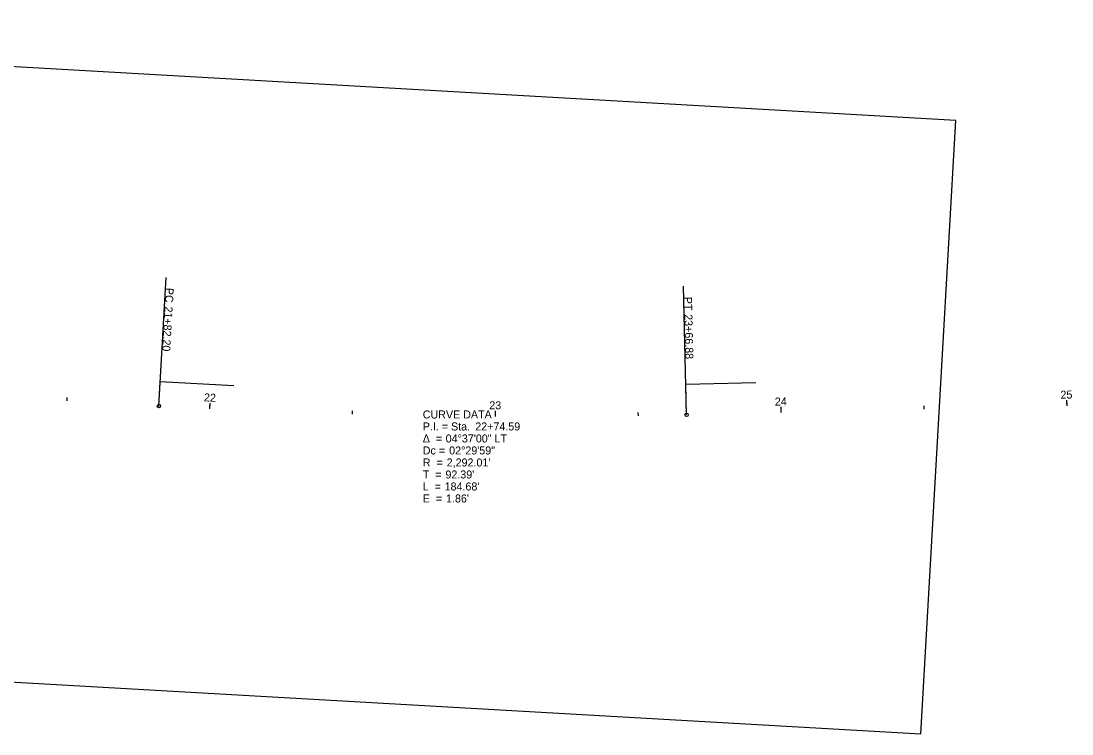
# Model space of a CAD drawing. Extents: x 2273904 to 2275374, y 654586 to 654897.
# Drawn here: x 2274639.3 to 2275006.9, y 654585.8 to 654835.2 of the extents above; entities that cross this region are included whole.
import ezdxf

# ---------------------------------------------------------------- set-up
doc = ezdxf.new("R2010")
doc.units = 0
for name, color, linetype in [('DR_P_Cells', 7, 'Continuous'), ('DR_P_Ditch', 7, 'Continuous'), ('DR_P_Erosion_Control', 7, 'Continuous'), ('GK_Drainage_Nodes', 7, 'Continuous'), ('SC_Scratch1', 7, 'Continuous'), ('SC_Scratch10', 7, 'Continuous'), ('SH_Named_Boundary', 7, 'Continuous')]:
    doc.layers.add(name, color=color, linetype=linetype)

msp = doc.modelspace()

# ---------------------------------------------------------------- linework, layer by layer
at = {"layer": 'DR_P_Ditch'}
for p, q in [((2274687.5, 654700.52), (2274690.07, 654745.45)), ((2274872.11, 654697.43), (2274871.05, 654742.42)), ((2274705.28, 654699.57), (2274705.34, 654700.77)), ((2275005.19, 654700.57), (2275005.15, 654702.57)), ((2274805.23, 654696.83), (2274805.24, 654698.03)), ((2274905.22, 654698.22), (2274905.19, 654699.42))]:
    msp.add_line(p, q, dxfattribs=at)
for centre in [(2274687.5, 654700.52), (2274872.11, 654697.43)]:
    msp.add_circle(centre, 0.6, dxfattribs=at)
at = {"layer": 'DR_P_Erosion_Control'}
for p, q in [((2274687.5, 654700.52), (2274690.07, 654745.45)), ((2274872.11, 654697.43), (2274871.05, 654742.42)), ((2274687.5, 654700.52), (2274687.99, 654709.04)), ((2274713.77, 654707.57), (2274687.99, 654709.04)), ((2274871.86, 654708.18), (2274896.32, 654708.76)), ((2274872.11, 654697.43), (2274871.86, 654708.18)), ((2274655.36, 654702.35), (2274655.43, 654703.55)), ((2274705.28, 654699.57), (2274705.38, 654701.57)), ((2275005.19, 654700.57), (2275005.15, 654702.57)), ((2274755.24, 654697.66), (2274755.28, 654698.86)), ((2274805.23, 654696.83), (2274805.25, 654698.83)), ((2274855.23, 654697.1), (2274855.21, 654698.3)), ((2274905.22, 654698.22), (2274905.17, 654700.21)), ((2274955.21, 654699.39), (2274955.18, 654700.59))]:
    msp.add_line(p, q, dxfattribs=at)
for centre in [(2274687.5, 654700.52), (2274687.5, 654700.52), (2274872.11, 654697.43), (2274872.11, 654697.43)]:
    msp.add_circle(centre, 0.6, dxfattribs=at)
at = {"layer": 'SC_Scratch1'}
for p, q in [((2274687.5, 654700.52), (2274690.07, 654745.45)), ((2274872.11, 654697.43), (2274871.05, 654742.42)), ((2275005.19, 654700.57), (2275005.16, 654701.77))]:
    msp.add_line(p, q, dxfattribs=at)
for centre in [(2274687.5, 654700.52), (2274872.11, 654697.43)]:
    msp.add_circle(centre, 0.6, dxfattribs=at)
at = {"layer": 'SH_Named_Boundary'}
msp.add_lwpolyline([(2274345.01, 654620.55), (2274954.02, 654585.8), (2274966.26, 654800.45), (2274357.26, 654835.2)], close=True, dxfattribs=at)

# ---------------------------------------------------------------- texts
at = {"layer": 'DR_P_Cells'}
for s, p in [('CURVE DATA', (2274779.81, 654696.18)), ('P.I. = Sta. ', (2274779.81, 654691.98)), ('22+74.59', (2274798.18, 654691.98)), ('Δ  = ', (2274779.81, 654687.78)), ('04°37\'00" LT', (2274787.83, 654687.78)), ('Dc = ', (2274779.81, 654683.58)), ('02°29\'59"', (2274789.05, 654683.58)), ('R  = ', (2274779.81, 654679.38)), ("2,292.01'", (2274788.18, 654679.38)), ('T  = ', (2274779.81, 654675.18)), ("92.39'", (2274787.74, 654675.18)), ('L  = ', (2274779.81, 654670.98)), ("184.68'", (2274787.45, 654670.98)), ('E  = ', (2274779.81, 654666.78)), ("1.86'", (2274787.96, 654666.78))]:
    msp.add_text(s, height=2.8, dxfattribs=at).set_placement(p)
at = {"layer": 'DR_P_Ditch'}
for s, rotation, p in [('PC', 266.7343, (2274689.92, 654741.94)), ('PT', 271.351, (2274871.18, 654738.69)), ('21+82.20', 266.7343, (2274689.54, 654735.43)), ('23+66.88', 271.351, (2274871.33, 654732.61)), ('25', 1.351, (2275002.93, 654703.07))]:
    msp.add_text(s, height=2.8, rotation=rotation, dxfattribs=at).set_placement(p)
at = {"layer": 'DR_P_Erosion_Control'}
for s, rotation, p in [('PC', 266.7343, (2274689.92, 654741.94)), ('PT', 271.351, (2274871.18, 654738.69)), ('21+82.20', 266.7343, (2274689.54, 654735.43)), ('23+66.88', 271.351, (2274871.33, 654732.61)), ('22', 357.1793, (2274703.22, 654702.18)), ('25', 1.351, (2275002.93, 654703.07)), ('23', 359.6791, (2274803.07, 654699.39)), ('24', 1.351, (2274903.01, 654700.66))]:
    msp.add_text(s, height=2.8, rotation=rotation, dxfattribs=at).set_placement(p)
at = {"layer": 'GK_Drainage_Nodes'}
for s, p in [('CURVE DATA', (2274779.81, 654696.18)), ('P.I. = Sta. ', (2274779.81, 654691.98)), ('22+74.59', (2274798.18, 654691.98)), ('Δ  = ', (2274779.81, 654687.78)), ('04°37\'00" LT', (2274787.83, 654687.78)), ('Dc = ', (2274779.81, 654683.58)), ('02°29\'59"', (2274789.05, 654683.58)), ('R  = ', (2274779.81, 654679.38)), ("2,292.01'", (2274788.18, 654679.38)), ('T  = ', (2274779.81, 654675.18)), ("92.39'", (2274787.74, 654675.18)), ('L  = ', (2274779.81, 654670.98)), ("184.68'", (2274787.45, 654670.98)), ('E  = ', (2274779.81, 654666.78)), ("1.86'", (2274787.96, 654666.78))]:
    msp.add_text(s, height=2.8, dxfattribs=at).set_placement(p)
at = {"layer": 'SC_Scratch1'}
for s, rotation, p in [('PC', 266.7343, (2274689.92, 654741.94)), ('PT', 271.351, (2274871.18, 654738.69)), ('21+82.20', 266.7343, (2274689.54, 654735.43)), ('23+66.88', 271.351, (2274871.33, 654732.61))]:
    msp.add_text(s, height=2.8, rotation=rotation, dxfattribs=at).set_placement(p)
at = {"layer": 'SC_Scratch10'}
for s, p in [('CURVE DATA', (2274779.81, 654696.18)), ('P.I. = Sta. ', (2274779.81, 654691.98)), ('22+74.59', (2274798.18, 654691.98)), ('Δ  = ', (2274779.81, 654687.78)), ('04°37\'00" LT', (2274787.83, 654687.78)), ('Dc = ', (2274779.81, 654683.58)), ('02°29\'59"', (2274789.05, 654683.58)), ('R  = ', (2274779.81, 654679.38)), ("2,292.01'", (2274788.18, 654679.38)), ('T  = ', (2274779.81, 654675.18)), ("92.39'", (2274787.74, 654675.18)), ('L  = ', (2274779.81, 654670.98)), ("184.68'", (2274787.45, 654670.98)), ('E  = ', (2274779.81, 654666.78)), ("1.86'", (2274787.96, 654666.78))]:
    msp.add_text(s, height=2.8, dxfattribs=at).set_placement(p)

doc.saveas('drawing.dxf')
